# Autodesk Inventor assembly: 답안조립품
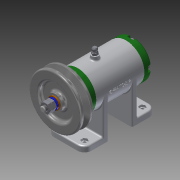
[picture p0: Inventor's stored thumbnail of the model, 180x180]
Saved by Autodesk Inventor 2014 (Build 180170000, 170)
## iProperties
Created: 2017-02
Part Number: 답안조립품
Document SubType Name: Assembly
Designer: user
Author: user
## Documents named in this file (13)
- C:\Users\user\Desktop\470208V1003\답안조립품.iam
- C:\Users\user\Desktop\470208V1003\본체.ipt
- C:\Users\user\Desktop\470208V1003\앞커버.ipt
- C:\Users\user\Desktop\470208V1003\뒤커버.ipt
- C:\Users\user\Desktop\470208V1003\볼트 M4 x 12.ipt
- C:\Users\user\Desktop\470208V1003\베어링 15 x 32 x 9.ipt
- C:\Users\user\Desktop\470208V1003\축.ipt
- C:\Users\user\Desktop\470208V1003\키 3 x 3 x 12.ipt
- C:\Users\user\Desktop\470208V1003\V벨트풀리.ipt
- C:\Users\user\Desktop\470208V1003\와셔 8x17.ipt
- C:\Users\user\Desktop\470208V1003\스프링와셔 8.ipt
- C:\Users\user\Desktop\470208V1003\너트 M 8.ipt
- C:\Users\user\Desktop\470208V1003\니플 M 6 x 0.75.ipt
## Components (11 placed, 3 different names)
1. KS B 2023 6002 - 15 x 32 x 9:1
2. KS B 2023 6002 - 15 x 32 x 9:2
3. V벨트풀리:1
4. ISO 4762 M4 x 12:1
5. ISO 4762 M4 x 12:3
6. ISO 4762 M4 x 12:4
7. ISO 4762 M4 x 12:5
8. ISO 4762 M4 x 12:2
9. ISO 4762 M4 x 12:6
10. ISO 4762 M4 x 12:7
11. ISO 4762 M4 x 12:8
